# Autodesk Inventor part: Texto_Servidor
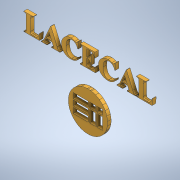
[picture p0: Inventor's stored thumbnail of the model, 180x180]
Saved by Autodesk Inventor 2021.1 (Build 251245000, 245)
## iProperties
Created: 2021-06
Part Number: Texto_Servidor
Material: Genérico
Document SubType Name: Modeling
Designer: Ricardo
Density: 1 g/cm^3
Appearance: Valor por defecto
Author: Ricardo
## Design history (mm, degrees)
sketch "Boceto1"
  geometry: L1 (-53, -8.046)-(-53, 21.997); L2 (-53, 21.997)-(53, 21.997); L3 (53, -8.046)-(-53, -8.046); L4 (53, 21.997)-(53, -8.046); L5 (-0.099, -20.405)-(-4.334, -20.405); L6 (-4.334, -17.57)-(-0.099, -17.57); L7 (-8.569, -15.348)-(-8.569, -13.93); L8 (-8.569, -13.93)-(-4.334, -13.93); L9 (-8.569, -16.765)-(-8.569, -15.348); L10 (-4.334, -16.765)-(-8.569, -16.765); L11 (-8.569, -17.57)-(-4.334, -17.57); L12 (-8.569, -18.988)-(-8.569, -17.57); L13 (-4.334, -20.405)-(-8.569, -20.405); L14 (-8.569, -20.405)-(-8.569, -18.988); L15 (8.021, -24.15)-(6.411, -24.15); L16 (6.411, -24.15)-(4.801, -24.15); L17 (4.801, -24.15)-(4.801, -20.86); L18 (8.021, -20.86)-(8.021, -24.15); L19 (-0.099, -18.988)-(-0.099, -20.405); L20 (8.021, -15.348)-(8.021, -16.765); L21 (8.021, -17.57)-(8.021, -20.86); L22 (-0.099, -13.93)-(-0.099, -15.348); L23 (-0.099, -15.348)-(-0.099, -16.765); L24 (-4.334, -13.93)-(-0.099, -13.93); L25 (-0.099, -16.765)-(-4.334, -16.765); L26 (0.741, -16.765)-(0.741, -15.348); L27 (0.741, -15.348)-(0.741, -13.93); L28 (0.741, -13.93)-(2.351, -13.93); L29 (2.351, -16.765)-(0.741, -16.765); L30 (3.961, -16.765)-(2.351, -16.765); L31 (3.961, -13.93)-(3.961, -15.348); L32 (2.351, -13.93)-(3.961, -13.93); L33 (8.021, -16.765)-(6.411, -16.765); L34 (6.411, -17.57)-(8.021, -17.57); L35 (6.411, -16.765)-(4.801, -16.765); L36 (4.801, -17.57)-(6.411, -17.57); L37 (4.801, -16.765)-(4.801, -15.348); L38 (3.961, -15.348)-(3.961, -16.765); L39 (4.801, -20.86)-(4.801, -17.57); L40 (3.961, -17.57)-(3.961, -20.86); L41 (4.801, -15.348)-(4.801, -13.93); L42 (4.801, -13.93)-(6.411, -13.93); L43 (8.021, -13.93)-(8.021, -15.348); L44 (6.411, -13.93)-(8.021, -13.93); L45 (-0.099, -21.245)-(-0.099, -22.698); L46 (0.741, -24.15)-(0.741, -20.86); L47 (-0.099, -22.698)-(-0.099, -24.15); L48 (-0.099, -24.15)-(-4.334, -24.15); L49 (-4.334, -21.245)-(-0.099, -21.245); L50 (-0.099, -17.57)-(-0.099, -18.988); L51 (3.961, -20.86)-(3.961, -24.15); L52 (3.961, -24.15)-(2.351, -24.15); L53 (2.351, -24.15)-(0.741, -24.15); L54 (0.741, -20.86)-(0.741, -17.57); L55 (0.741, -17.57)-(2.351, -17.57); L56 (2.351, -17.57)-(3.961, -17.57); L57 (-8.569, -21.245)-(-4.334, -21.245); L58 (-8.569, -22.698)-(-8.569, -21.245); L59 (-4.334, -24.15)-(-8.569, -24.15); L60 (-8.569, -24.15)-(-8.569, -22.698); A1 r 11.125 centre (-0.243, -19.009) between (-6.708, -28.062) and (-4.536, -29.271); A2 r 10.854 centre (-0.348, -19.259) between (-4.536, -29.271) and (-2.164, -29.959); A3 r 12.046 centre (-0.148, -18.083) between (-2.164, -29.959) and (-1.695, -30.029); A4 r 8.551 centre (-0.597, -21.549) between (-1.695, -30.029) and (-1.262, -30.074); A5 r 9.448 centre (-0.527, -20.655) between (-1.262, -30.074) and (-0.808, -30.099); A6 r 17.951 centre (-0.274, -12.156) between (-0.808, -30.099) and (-0.274, -30.107); A7 r 9.448 centre (-0.021, -20.655) between (0.26, -30.099) and (0.714, -30.074); A8 r 17.951 centre (-0.274, -12.156) between (-0.274, -30.107) and (0.26, -30.099); A9 r 11.249 centre (-0.133, -19.126) between (-9.357, -12.686) and (-10.861, -15.741); A10 r 10.537 centre (-0.812, -18.911) between (-10.861, -15.741) and (-11.3, -17.894); A11 r 11.498 centre (0.144, -19.004) between (-11.3, -17.894) and (-11.297, -20.14); A12 r 8.551 centre (0.048, -21.549) between (0.714, -30.074) and (1.147, -30.029); A13 r 12.046 centre (-0.4, -18.083) between (1.147, -30.029) and (1.616, -29.959); A14 r 10.892 centre (-0.207, -19.221) between (1.616, -29.959) and (3.785, -29.355); A15 r 11.053 centre (-0.266, -19.071) between (3.785, -29.355) and (5.792, -28.316); A16 r 11.112 centre (-0.299, -19.022) between (5.792, -28.316) and (7.551, -26.887); A17 r 11.157 centre (-0.331, -18.99) between (7.551, -26.887) and (8.985, -25.13); A18 r 14.392 centre (-3.031, -17.209) between (8.985, -25.13) and (9.301, -24.629); A19 r 9.132 centre (1.476, -19.921) between (9.301, -24.629) and (9.56, -24.168); A20 r 8.9 centre (1.681, -20.029) between (9.56, -24.168) and (9.789, -23.699); A21 r 12.958 centre (-2.015, -18.356) between (9.789, -23.699) and (10.015, -23.17); A22 r 11.027 centre (-0.223, -19.073) between (10.015, -23.17) and (10.663, -20.831); A23 r 11.241 centre (-0.435, -19.039) between (10.663, -20.831) and (10.788, -18.394); A24 r 11.202 centre (-0.395, -19.037) between (10.788, -18.394) and (10.385, -15.992); A25 r 8.216 centre (-0.362, -16.178) between (-0.162, -7.964) and (-0.694, -7.969); A26 r 14.839 centre (-0.524, -22.799) between (0.455, -7.992) and (-0.162, -7.964); A27 r 14.998 centre (-0.534, -22.958) between (1.074, -8.046) and (0.455, -7.992); A28 r 8.962 centre (0.113, -16.956) between (1.616, -8.121) and (1.074, -8.046); A29 r 10.864 centre (-0.206, -18.832) between (4, -8.814) and (1.616, -8.121); A30 r 11.158 centre (-0.319, -19.102) between (6.182, -10.034) and (4, -8.814); A31 r 11.255 centre (-0.239, -19.215) between (-0.694, -7.969) and (-4.038, -8.62); A32 r 11.025 centre (-0.317, -18.998) between (-4.038, -8.62) and (-7.013, -10.239); A33 r 11.023 centre (-0.318, -18.997) between (-7.013, -10.239) and (-9.357, -12.686); A34 r 10.855 centre (-0.061, -18.942) between (10.385, -15.992) and (9.474, -13.755); A35 r 11.043 centre (-0.226, -19.032) between (9.474, -13.755) and (8.041, -11.712); A36 r 11.199 centre (-0.343, -19.136) between (8.041, -11.712) and (6.182, -10.034); A37 r 11.48 centre (0.126, -19.006) between (-11.297, -20.14) and (-10.858, -22.341); A38 r 10.459 centre (-0.851, -19.303) between (-10.858, -22.341) and (-10.005, -24.36); A39 r 11.212 centre (-0.191, -18.938) between (-10.005, -24.36) and (-8.564, -26.396); A40 r 11.206 centre (-0.196, -18.942) between (-8.564, -26.396) and (-6.708, -28.062); 102 further points
  constraints: 112 end point, 80 point on circle, 40 centre point, 2 midpoint, 2 other
extrude "Extrusión1" new body sketch "Boceto1" distance "d0" = 2; taper "d1" = 0 deg
node "Sólido1"
